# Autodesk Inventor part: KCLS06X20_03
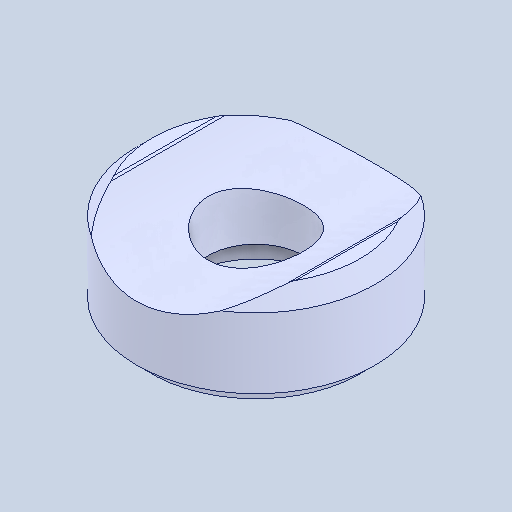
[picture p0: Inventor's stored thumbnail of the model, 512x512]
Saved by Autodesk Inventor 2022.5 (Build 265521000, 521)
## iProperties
Created: 2024-08
Part Number: KCLS06X20_03
Material: 一般
Document SubType Name: Modeling
Designer: ImaoCorp
Density: 1 g/cm^3
Appearance: 既定
Author: ImaoCorp
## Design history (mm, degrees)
feature "KCLS06X20_03"
node "ソリッド1"
